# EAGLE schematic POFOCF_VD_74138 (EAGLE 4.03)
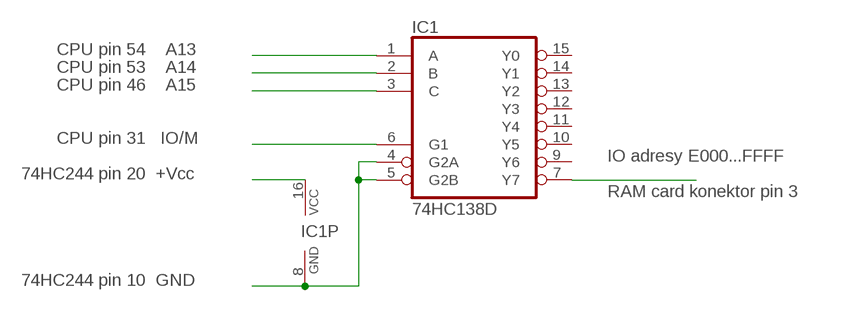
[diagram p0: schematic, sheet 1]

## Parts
IC1  74HC138D  [SO16]

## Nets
N$1: IC1.4(G2A) IC1.5(G2B) IC1.8(GND)
N$4: IC1.3(C)
N$5: IC1.6(G1)
N$6: IC1.2(B)
N$7: IC1.1(A)
N$8: IC1.7(Y7)
N$9: IC1.16(VCC)
Unconnected: IC1.9(Y6) IC1.10(Y5) IC1.11(Y4) IC1.12(Y3) IC1.13(Y2) IC1.14(Y1) IC1.15(Y0)

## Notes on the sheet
- CPU pin 54    A13
- CPU pin 53    A14
- CPU pin 46    A15
- CPU pin 31   IO/M
- IO adresy E000...FFFF
- 74HC244 pin 20  +Vcc
- RAM card konektor pin 3
- 74HC244 pin 10  GND

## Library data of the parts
IC1 = 74xx-eu:74*138: 3-line to 8-line DECODER/DEMULTIPLEXER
